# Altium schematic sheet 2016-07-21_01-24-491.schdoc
size 455 x 184 mm; SheetNumber: 1; SheetTotal: 1
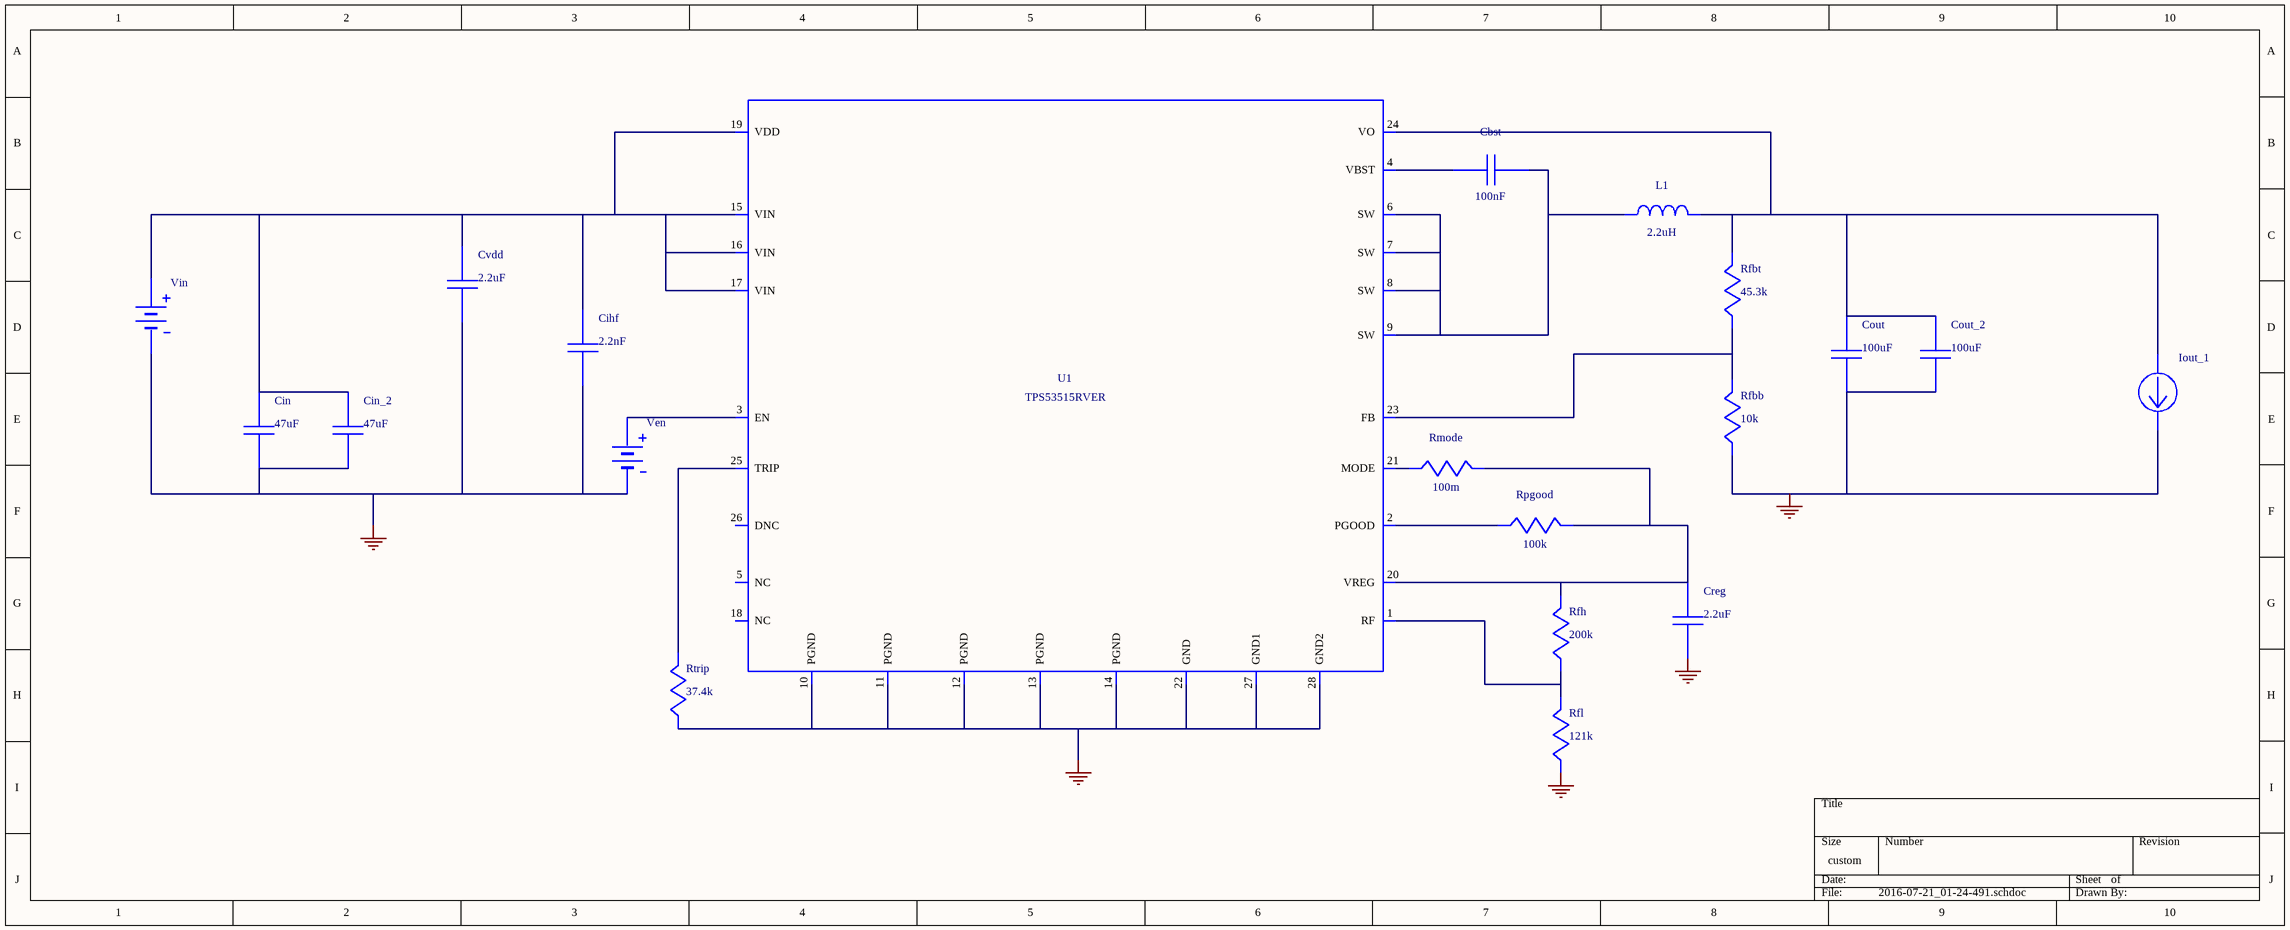
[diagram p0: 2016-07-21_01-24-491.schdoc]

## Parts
Cbst  value 100nF  (hidden comment: C0805C104K5RACTU)
Cihf  value 2.2nF  (hidden comment: GRM155R61E222KA01D)
Cin  value 47uF  (hidden comment: GRM31CR61A476KE15L)
Cin_2  value 47uF  (hidden comment: GRM31CR61A476KE15L)
Cout  value 100uF  (hidden comment: GRM31CR60J107ME39L)
Cout_2  value 100uF  (hidden comment: GRM31CR60J107ME39L)
Creg  value 2.2uF  (hidden comment: GRM21BR61E225KA12L)
Cvdd  value 2.2uF  (hidden comment: GRM21BR61E225KA12L)
Iout_1  WB_CURRENT_LOAD  (value not drawn)
L1  value 2.2uH  (hidden comment: XAL5030-222MEB)
Rfbb  value 10k  (hidden comment: CRCW040210K0FKED)
Rfbt  value 45.3k  (hidden comment: CRCW040245K3FKED)
Rfh  value 200k  (hidden comment: CRCW0402200KFKED)
Rfl  value 121k  (hidden comment: CRCW0402121KFKED)
Rmode  value 100m  (hidden comment: ERJ-3RSFR10V)
Rpgood  value 100k  (hidden comment: CRCW0402100KFKED)
Rtrip  value 37.4k  (hidden comment: CRCW040237K4FKED)
U1  TPS53515RVER
Ven  WB_PRIM_DC_VOLTAGE_SOURCE  (value not drawn)
Vin  WB_BATTERY  (value not drawn)

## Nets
0: Cihf.2 Cin.2 Cin_2.2 Cout.2 Cout_2.2 Creg.1 Cvdd.2 Iout_1.2(-) Rfbb.2 Rfl.2 Rtrip.2 U1.10(PGND) U1.11(PGND) U1.12(PGND) U1.13(PGND) U1.14(PGND) U1.22(GND) U1.27(GND1) U1.28(GND2) U1.29(ETPAD) Ven.2(-) Vin.2(-)
NetCbst_1: Cbst.1 U1.4(VBST)
NetCbst_2: Cbst.2 L1.2 U1.6(SW) U1.7(SW) U1.8(SW) U1.9(SW)
NetCihf_1: Cihf.1 Cin.1 Cin_2.1 Cvdd.1 U1.15(VIN) U1.16(VIN) U1.17(VIN) U1.19(VDD) Vin.1(+)
NetCout_1: Cout.1 Cout_2.1 Iout_1.1(+) L1.1 Rfbt.1 U1.24(VO)
NetCreg_2: Creg.2 Rfh.1 Rmode.1 Rpgood.1 U1.20(VREG)
NetRfbb_1: Rfbb.1 Rfbt.2 U1.23(FB)
NetRfh_2: Rfh.2 Rfl.1 U1.1(RF)
NetRmode_2: Rmode.2 U1.21(MODE)
NetRpgood_2: Rpgood.2 U1.2(PGOOD)
NetRtrip_1: Rtrip.1 U1.25(TRIP)
NetU1_3: U1.3(EN) Ven.1(+)

Not connected (* = marked no-connect by the designer): U1 5(NC) 18(NC) 26(DNC)

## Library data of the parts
Cbst = C0805C104K5RACTU: Manufacturer Name: Kemet
Cihf = GRM155R61E222KA01D: GRM155R61E222KA0; Manufacturer Name: MuRata
Cin Cin_2 = GRM31CR61A476KE15L: GRM31CR61A476KE1; Manufacturer Name: MuRata
Cout Cout_2 = GRM31CR60J107ME39L: GRM31CR60J107ME3; Manufacturer Name: MuRata
Creg Cvdd = GRM21BR61E225KA12L: GRM21BR61E225KA1; Manufacturer Name: MuRata
L1 = XAL5030-222MEB: Manufacturer Name: Coilcraft
Rfbb = CRCW040210K0FKED: Manufacturer Name: Vishay-Dale
Rfbt = CRCW040245K3FKED: Manufacturer Name: Vishay-Dale
Rfh = CRCW0402200KFKED: Manufacturer Name: Vishay-Dale
Rfl = CRCW0402121KFKED: Manufacturer Name: Vishay-Dale
Rmode = ERJ-3RSFR10V: Manufacturer Name: Panasonic
Rpgood = CRCW0402100KFKED: Manufacturer Name: Vishay-Dale
Rtrip = CRCW040237K4FKED: Manufacturer Name: Vishay-Dale
U1 = TPS53515RVER: Manufacturer Name: Texas Instruments
Ven = WB_PRIM_DC_VOLTAGE_SOURCE: WB_PRIM_DC_VOLTA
